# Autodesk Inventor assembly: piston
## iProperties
Shininess: 64.0
Length Units: 11269
Angle Units: 11279
Time Units: 11290
Mass Units: 11283
Length Display Precision: 3
Angle Display Precision: 2
Compacted: True
Created: 2005-01
Part Number: piston
Document SubType Name: Assembly
Designer: David
Manufacturer: Standard
Standards Organization: Custom
Density: 0.0
Volumn: 0.0
Area: 0.0
PropertySet Name: Model Information
Control State: 0
Master: False
Checked Out: False
Author: David
